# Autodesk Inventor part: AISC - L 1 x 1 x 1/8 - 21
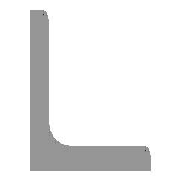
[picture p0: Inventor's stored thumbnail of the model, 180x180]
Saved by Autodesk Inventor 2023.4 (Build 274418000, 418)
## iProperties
Created: 2022-02
Part Number: AISC - L 1 x 1 x 1/8 - 21
Material: Steel, Mild
Description: Angle Steel
Document SubType Name: Modeling
Standard: AISC
Designer: Fred L.
Standards Organization: ANSI
Language: en-US
Size Designation: (L 1 x 1 x 1/8)
Categories: <MemberInstance><Categories><Category DisplayName="Structural Shapes" InternalName="089c4875-fa83-4c05-b084-43b9cc11f5ed" Mnemonic="GRDR"><CategoryParameter Dis
Stock Number: (L 1 x 1 x 1/8)
Mass: 638.766 g
Surface Area: 530.448 cm^2
Volume: 81.3714 cm^3
Density: 7.85 g/cm^3
Appearance: Semi-Polished
IsCustomPart: 1
G_L: 21.000 in
G_W: 1.000 in
G_H: 1.000 in
Mass: 1.41
SurfaceArea: 82.22
+4A91A003-9ACF-4524-891B-5FEE60D6CC2A+CUTDETAIL1: Corner Joint
+BC6EA230-662A-4952-B540-0E13420F9ACB+CUTDETAIL2: Corner Joint
_CCFamilyMember: 1
_CCFamilyDisplayName: ANSI L (Equal angles) - Angle Steel — Sizes in parentheses have been withdrawn
_FrameMemberDoc: Frame Member File
_Version: 25.0.0
_GetPNFromCC: 1
Author: Fred L.
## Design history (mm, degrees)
node "Start Plane"
node "End Plane"
sketch "Sketch"
  geometry: L1 (25.4, 0)-(0, 0); L2 (0, 0)-(0, 25.4); L3 (0, 25.4)-(1.651, 25.4); L4 (3.175, 23.876)-(3.175, 6.477); L5 (6.477, 3.175)-(23.876, 3.175); L6 (25.4, 1.651)-(25.4, 0); L7 (0, -11.041)-(0, 31.538); L8 (-11.041, 0)-(31.538, 0); L9 (0, 40.054)-(0, -19.557) reference; L10 (-19.557, 0)-(40.054, 0) reference; A1 r 3.302 centre (6.477, 6.477) between (3.175, 6.477) and (6.477, 3.175); A2 r 1.524 centre (1.651, 23.876) between (3.175, 23.876) and (1.651, 25.4); A3 r 1.524 centre (23.876, 1.651) between (25.4, 1.651) and (23.876, 3.175); 3 further points
  constraints: 16 end point, 6 point on circle, 6 point on line, 6 tangent, 4 parallel, 3 centre point, 2 collinear, 1 equal radius, 1 horizontal, 1 perpendicular
  dimensions: "d0" = 25.4 distance between parallel lines of L6 L2 (= G_H); "d1" = 25.4 distance between parallel lines of L3 L1 (= G_H); "d2" = 3.175 distance between parallel lines of L2 L4 (= G_T); "d3" = 3.175 distance between parallel lines of L1 L5 (= G_T); "d10" = 0 distance between parallel lines of L7 L2 (computed from ex); "d11" = 0 distance between parallel lines of L8 L1 (computed from d10); "d14" = 3.302 radius of A1 (= G_IR); "d15" = 1.524 radius of A2 (= G_ER)
extrude "Body" new body sketch "Sketch" stored distance "d4" = 533.4 (= G_L); taper "d5" = 0 deg
node "Driven Length"
  sketch "Sketch3"
    geometry: L1 (0, 0)-(10, 0) reference
    constraints: 2 end point, 1 horizontal
  workplane "Work Plane3"
workplane "Work Plane4"
split "Split1"
workplane "Work Plane5"
split "Split2"
body "Solid1"
sketch "Sketch4"
  geometry: L1 (-2, -12.7)-(12, -12.7) reference; L2 (-2, 520.7)-(12, 520.7) reference
  dimensions: "d17" = 533.4 distance between parallel lines of L1 L2 (derived)
other parameters: "G_H" = 25.4 [user parameter; used in 2 equation terms], "G_T" = 3.175 [user parameter; used in 2 equation terms], "G_ER" = 1.524 [user parameter; used in 1 equation term], "G_IR" = 3.302 [user parameter; used in 1 equation term], "G_L" = 533.4 (= d17) [user parameter; used in 1 equation term], "ex" = 0 [user parameter; used in 1 equation term], "G_OFFSET_START" = 12.7 [user parameter; used in 1 equation term], "G_OFFSET_END" = 12.7 [user parameter; used in 1 equation term], "d12" = -12.7 (= -G_OFFSET_START), "d13" = 520.7 (= G_OFFSET_END + B_L), "B_L" = 508 [user parameter; used in 1 equation term], "d16" = 90 deg, "MAS" = 0.11905 [user parameter]
